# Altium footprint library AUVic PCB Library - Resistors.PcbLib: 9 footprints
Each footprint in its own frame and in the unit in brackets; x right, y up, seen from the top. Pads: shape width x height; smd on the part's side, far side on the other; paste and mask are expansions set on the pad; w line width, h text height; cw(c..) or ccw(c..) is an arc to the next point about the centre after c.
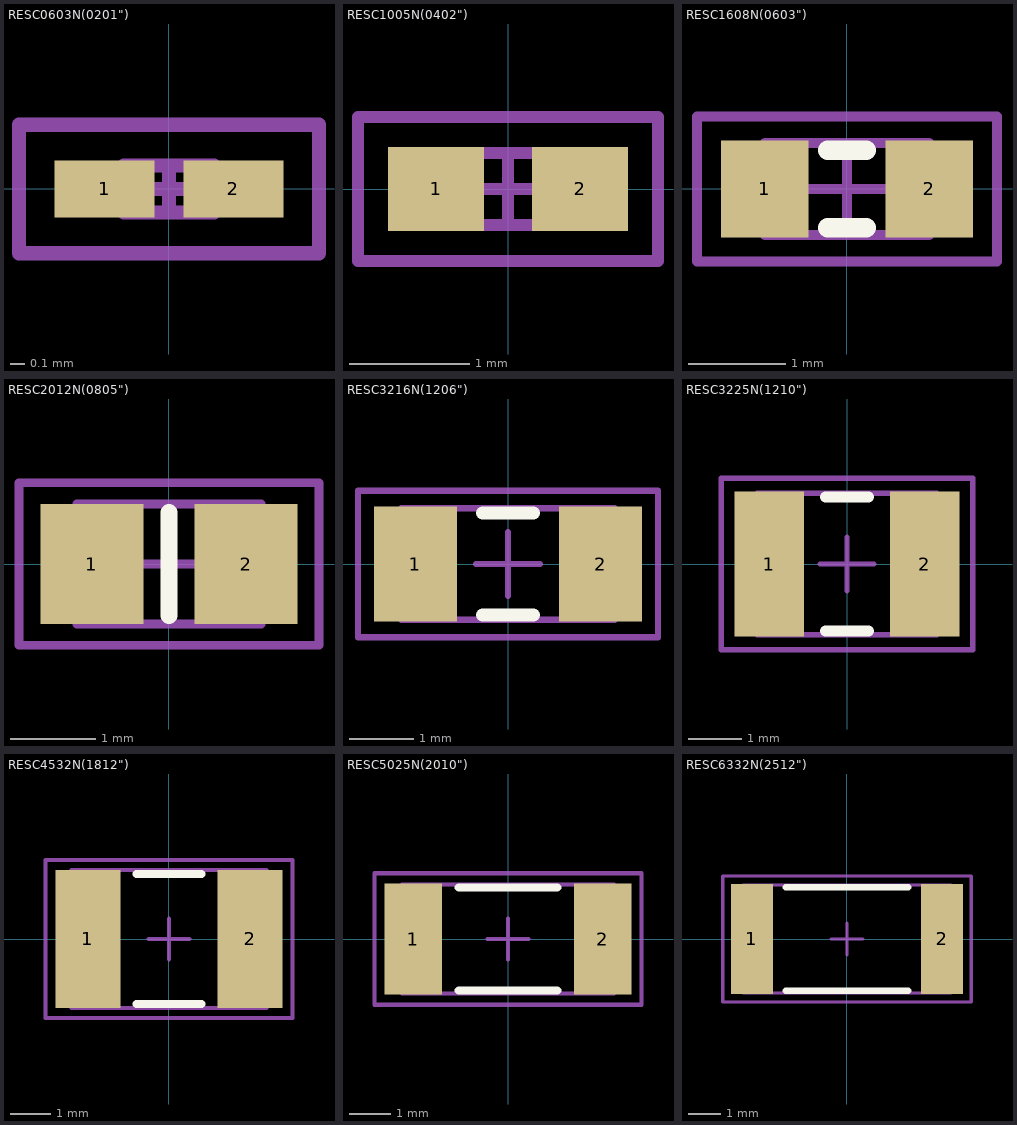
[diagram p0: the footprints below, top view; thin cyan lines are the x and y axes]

## RESC0603N(0201") [mm] "Chip Resistor, Body 0.6x0.3mm (0201\"), IPC Medium Density"
height 0.3
pads (2):
  rect 0.7x0.4 smd: 1(-0.45,0) 2(0.45,0)
Mechanical 13:
  lines w0.1: -0.315,-0.165 -0.315,0.165 0.315,0.165 0.315,-0.165 -0.315,-0.165
Mechanical 15:
  lines w0.1: -0.165,0 0.165,0 ; 0,-0.165 0,0.165 ; -1.05,-0.45 -1.05,0.45 1.05,0.45 1.05,-0.45 -1.05,-0.45
3D body: height 0.3, standoff 0, extent -0.315,-0.165 0.315,0.165

## RESC1005N(0402") [mm] "Chip Resistor, Body 1.1x0.5mm (0402\"), IPC Medium Density"
height 0.4
pads (2):
  rect 0.8x0.7 smd: 1(-0.6,0) 2(0.6,0)
Mechanical 13:
  lines w0.1: -0.55,-0.3 0.55,-0.3 0.55,0.3 -0.55,0.3 -0.55,-0.3
Mechanical 15:
  lines w0.1: -0.3,0 0.3,0 ; 0,-0.3 0,0.3 ; -1.25,-0.6 1.25,-0.6 1.25,0.6 -1.25,0.6 -1.25,-0.6
3D body: height 0.4, standoff 0, extent -0.55,-0.3 0.55,0.3

## RESC1608N(0603") [mm] "Chip Resistor, Body 1.6x0.8mm (0603\"), IPC Medium Density"
height 0.6
pads (2):
  rect 0.9x1 smd: 1(-0.85,0) 2(0.85,0)
Top Overlay:
  lines w0.2: -0.2,-0.4 0.2,-0.4 ; -0.2,0.4 0.2,0.4
Mechanical 13:
  lines w0.1: -0.85,-0.475 0.85,-0.475 0.85,0.475 -0.85,0.475 -0.85,-0.475
Mechanical 15:
  lines w0.1: -0.475,0 0.475,0 ; 0,-0.475 0,0.475 ; -1.55,-0.75 1.55,-0.75 1.55,0.75 -1.55,0.75 -1.55,-0.75
3D body: height 0.6, standoff 0, extent -0.85,-0.475 0.85,0.475

## RESC2012N(0805") [mm] "Chip Resistor, Body 2.0x1.3mm (0805\"), IPC Medium Density"
height 0.65
pads (2):
  rect 1.2x1.4 smd: 1(-0.9,0) 2(0.9,0)
Top Overlay:
  lines w0.2: 0,-0.6 0,0.6
Mechanical 13:
  lines w0.1: -1.075,-0.7 1.075,-0.7 1.075,0.7 -1.075,0.7 -1.075,-0.7
Mechanical 15:
  lines w0.1: -0.5,0 0.5,0 ; 0,-0.5 0,0.5 ; -1.75,-0.95 1.75,-0.95 1.75,0.95 -1.75,0.95 -1.75,-0.95
3D body: height 0.65, standoff 0, extent -1.075,-0.7 1.075,0.7

## RESC3216N(1206") [mm] "Chip Resistor, Body 3.2x1.6mm(1206\"), IPC Medium Density"
height 0.71
pads (2):
  rect 1.3x1.8 smd: 1(-1.45,0) 2(1.45,0)
Top Overlay:
  lines w0.2: -0.4,-0.8 0.4,-0.8 ; -0.4,0.8 0.4,0.8
Mechanical 13:
  lines w0.1: -1.675,-0.875 1.675,-0.875 1.675,0.875 -1.675,0.875 -1.675,-0.875
Mechanical 15:
  lines w0.1: -0.5,0 0.5,0 ; 0,-0.5 0,0.5 ; -2.35,-1.15 2.35,-1.15 2.35,1.15 -2.35,1.15 -2.35,-1.15
3D body: height 0.71, standoff 0, extent -1.675,-0.875 1.675,0.875

## RESC3225N(1210") [mm] "Chip Resistor, Body 3.2x2.5mm (1210\"), IPC Medium Density"
height 0.71
pads (2):
  rect 1.3x2.7 smd: 1(-1.45,0) 2(1.45,0)
Top Overlay:
  lines w0.2: -0.4,-1.25 0.4,-1.25 ; -0.4,1.25 0.4,1.25
Mechanical 13:
  lines w0.1: -1.675,-1.32 1.675,-1.32 1.675,1.32 -1.675,1.32 -1.675,-1.32
Mechanical 15:
  lines w0.1: -0.5,0 0.5,0 ; 0,-0.5 0,0.5 ; -2.35,-1.6 2.35,-1.6 2.35,1.6 -2.35,1.6 -2.35,-1.6
3D body: height 0.71, standoff 0, extent -1.675,-1.32 1.675,1.32

## RESC4532N(1812") [mm] "Chip Resistor, Body 4.5x3.2mm (1812\"), IPC Medium Density"
height 0.71
pads (2):
  rect 1.6x3.4 smd: 1(-2,0) 2(2,0)
Top Overlay:
  lines w0.2: -0.8,-1.6 0.8,-1.6 ; -0.8,1.6 0.8,1.6
Mechanical 13:
  lines w0.1: -2.4,-1.7 2.4,-1.7 2.4,1.7 -2.4,1.7 -2.4,-1.7
Mechanical 15:
  lines w0.1: -0.5,0 0.5,0 ; 0,-0.5 0,0.5 ; -3.05,-1.95 3.05,-1.95 3.05,1.95 -3.05,1.95 -3.05,-1.95
3D body: height 0.71, standoff 0, extent -2.4,-1.7 2.4,1.7

## RESC5025N(2010") [mm] "Chip Resistor, Body 5.0x2.5mm (2010\"), IPC Medium Density"
height 0.71
pads (2):
  rect 1.4x2.7 smd: 1(-2.3,0) 2(2.3,0)
Top Overlay:
  lines w0.2: -1.2,-1.25 1.2,-1.25 ; -1.2,1.25 1.2,1.25
Mechanical 13:
  lines w0.1: -2.575,-1.325 -2.575,1.325 2.575,1.325 2.575,-1.325 -2.575,-1.325
Mechanical 15:
  lines w0.1: -0.5,0 0.5,0 ; 0,-0.5 0,0.5 ; -3.25,-1.6 -3.25,1.6 3.25,1.6 3.25,-1.6 -3.25,-1.6
3D body: height 0.71, standoff 0, extent -2.575,-1.325 2.575,1.325

## RESC6332N(2512") [mm] "Chip Resistor, Body 6.3x3.2mm (2512\"), IPC Medium Density"
height 0.71
pads (2):
  rect 1.3x3.4 smd: 1(-2.95,0) 2(2.95,0)
Top Overlay:
  lines w0.2: -1.9,-1.6 1.9,-1.6 ; -1.9,1.6 1.9,1.6
Mechanical 13:
  lines w0.1: -3.225,-1.675 3.225,-1.675 3.225,1.675 -3.225,1.675 -3.225,-1.675
Mechanical 15:
  lines w0.1: -0.5,0 0.5,0 ; 0,-0.5 0,0.5 ; -3.85,-1.95 3.85,-1.95 3.85,1.95 -3.85,1.95 -3.85,-1.95
3D body: height 0.71, standoff 0, extent -3.225,-1.675 3.225,1.675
